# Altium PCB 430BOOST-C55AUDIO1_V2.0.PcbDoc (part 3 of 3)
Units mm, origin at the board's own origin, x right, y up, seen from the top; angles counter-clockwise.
Board outline 50.8 x 84 mm, 4 copper layers (Top Layer, GND, POW, Bottom Layer); 272 components, 169 nets, 833 pads, 607 vias.
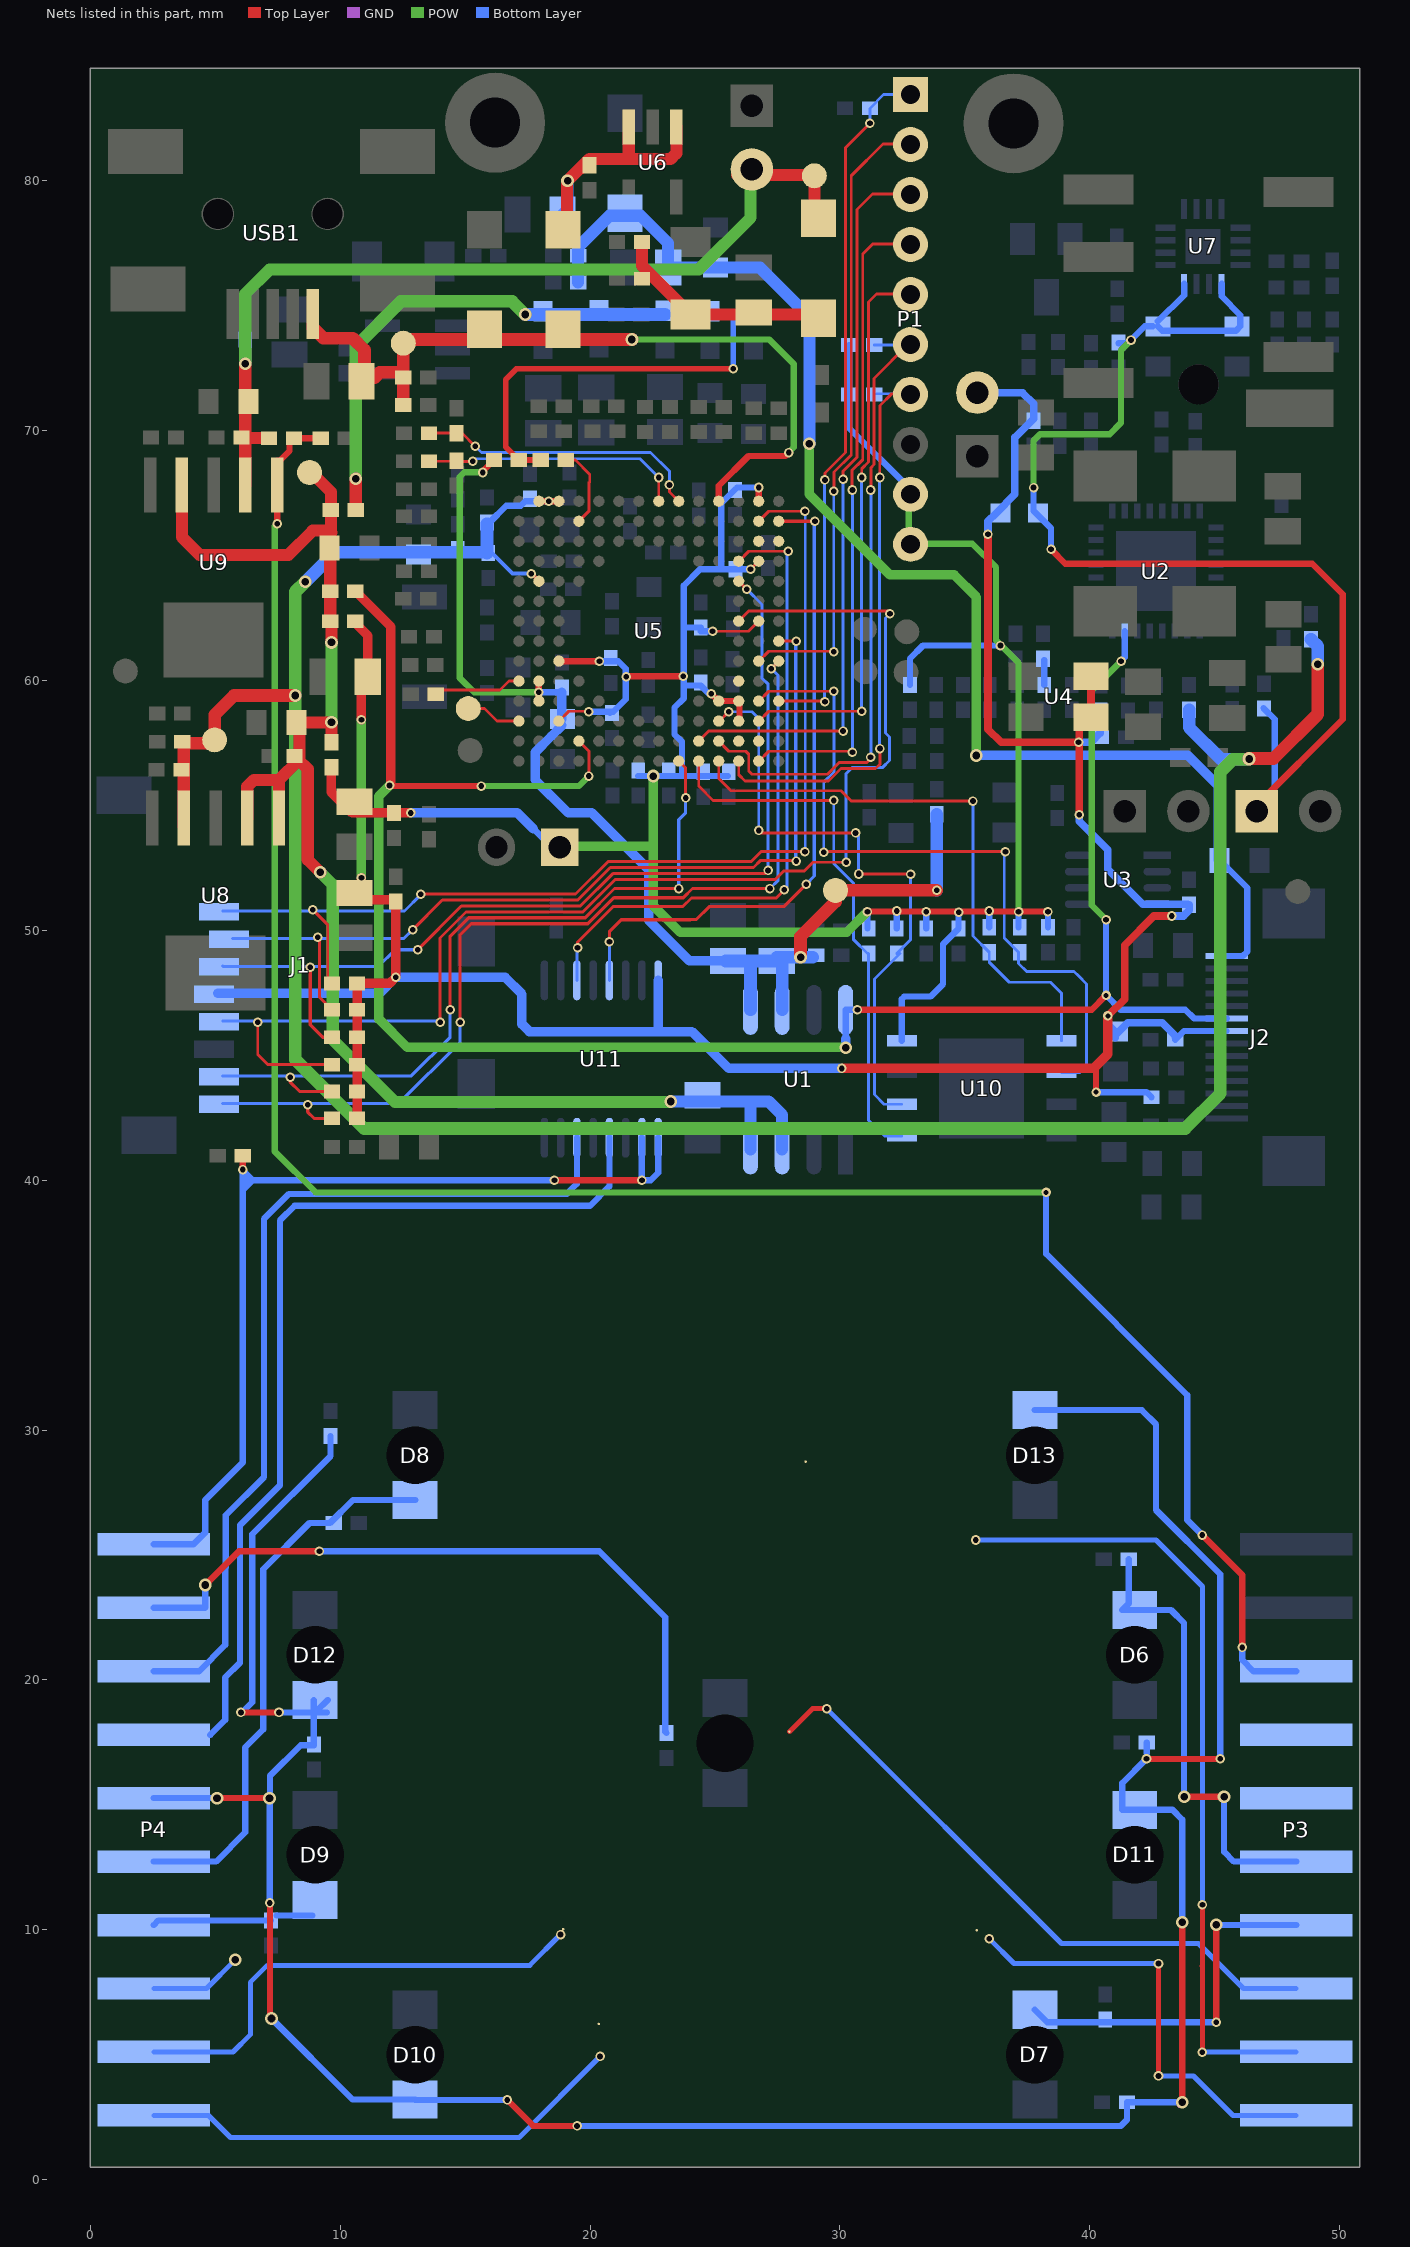
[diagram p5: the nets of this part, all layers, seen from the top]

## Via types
v1: diameter 0.381, hole 0.229, Top Layer to Bottom Layer, 549 vias
v2: diameter 0.508, hole 0.305, Top Layer to Bottom Layer, 42 vias
v3: diameter 0.381, hole 0.203, Top Layer to Bottom Layer, 16 vias

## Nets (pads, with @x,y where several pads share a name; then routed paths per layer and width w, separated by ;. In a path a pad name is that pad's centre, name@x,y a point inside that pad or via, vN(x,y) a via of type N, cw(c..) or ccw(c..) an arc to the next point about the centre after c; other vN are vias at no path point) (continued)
P1.0: P4.2 R87.2 | length 28
  Top Layer w0.25: v2(4.6,23.8) 5.95,25.15 8.6,25.15 v1(9.17,25.15)
  Bottom Layer w0.25: P4.2@2.54,22.89 4.59,22.89 4.6,22.9 v2(4.6,23.8) ; v1(9.17,25.15) 15.06,25.15 ; 15.43,25.15 15.06,25.15 ; R87.2@23.06,17.88 23.01,17.93 23.01,22.51 20.37,25.15 15.06,25.15
P1.1_RX: P4.3 U11.6 | length 36.3
  Bottom Layer w0.25: P4.3@2.54,20.35 4.35,20.35 5.4,21.4 5.4,24.48 5.42,24.5 5.42,26.59 6.95,28.12 6.95,33.9 ; 6.95,34.252 6.95,33.9 ; U11.6@19.475,41.7 19.475,39.85 19.075,39.45 7.95,39.45 6.95,38.45 6.95,33.9
P1.2_TX: P4.4 U11.4 | length 37.4
  Bottom Layer w0.25: 4.8,17.8 5.4,18.4 5.4,20.1 5.99,20.69 5.99,26.19 7.59,27.79 7.59,38.39 8.175,38.975 20,38.975 20.775,39.75 U11.4@20.775,41.7
P1.3: D10.2 D11.2 D12.2 D13.2 P4.5 R83.1 R84.1 R85.1 R86.1 | length 113.5
  Top Layer w0.25: v2(5.07,15.27) v2(7.17,15.27) ; v1@6.05,18.7 v1(7.55,18.7) ; v1@7.19,11.075 7.19,6.51 v2(7.25,6.45) ; v1(16.69,3.19) 17.73,2.15 v1(19.48,2.15) ; v1(42.27,16.84) v1(45.22,16.84) ; v2(43.7,3.1) v2(43.7,10.3)
  GND w0.25: v2(7.17,15.27) v2@7.2,15.3 ; v2@43.6,3 v2(43.7,3.1)
  Bottom Layer w0.25: P4.5@2.54,15.27 v2(5.07,15.27) ; v1(6.025,18.7) 6.075,18.7 6.48,19.105 6.48,25.83 9.61,28.96 R84.1@9.61,29.76 ; v1(7.175,11.075) v2@7.175,15.255 ; v2@7.19,15.27 7.19,16.16 8.42,17.39 R85.1@8.95,17.39 ; v2(7.25,6.45) 10.49,3.21 12.99,3.21 D10.2@13,3.2 13.01,3.19 v1(16.69,3.19) ; v1(7.55,18.7) D12.2@9.47,18.7 ; R85.1@8.94,17.39 D12.2@8.94,19.19 ; D12.2@9.04,18.74 9.49,19.19 D12.2@9.5,19.2 ; v1(19.48,2.15) 41.25,2.15 41.49,2.39 R86.1@41.49,3.1 v2(43.7,3.1) ; D13.2@37.8,30.8 42.075,30.8 42.65,30.225 42.65,26.8 45.22,24.23 v1(45.22,16.84) ; v1@42.28,16.84 42.28,16.85 v1(42.27,16.84) 41.3,15.87 41.3,14.8 D11.2@41.8,14.8 43.31,14.8 43.7,14.41 43.7,10.58 v2(43.7,10.3) ; 42.28,17.07 R83.1@42.28,17.5
P1.4: D8.2 P4.6 R15.2 | length 22.2
  Bottom Layer w0.25: P4.6@2.54,12.73 5.03,12.73 6.2,13.9 6.2,17.3 6.92,18.02 6.92,24.43 8.77,26.28 9.59,26.28 10.51,27.2 D8.2@13,27.2
P1.5: D9.2 P4.7 R17.2 | length 6.2
  Bottom Layer w0.25: P4.7@2.54,10.19 2.725,10.375 6.1,10.375 R17.2@7.225,10.375 ; R17.2@7.45,10.575 D9.2@8.89,10.575
P1.6: D7.2 P3.7 R18.2 | length 14.6
  Top Layer w0.25: v1(45.06,6.3) 45.06,9.3 v2(45.06,10.2)
  Bottom Layer w0.25: D7.2@37.8,6.8 38.3,6.3 v1(45.06,6.3) ; v2(45.06,10.2) 45.07,10.19 P3.7@48.26,10.19
P1.7: D6.2 P3.6 R78.2 | length 18.6
  Top Layer w0.25: v2(43.775,15.325) v2(45.375,15.325)
  Bottom Layer w0.25: R78.2@41.56,24.83 41.56,23.06 41.3,22.8 D6.2@41.8,22.8 43.25,22.8 43.775,22.275 43.775,18.5 43.775,16.375 v2(43.775,15.325) ; v2(45.375,15.325) 45.375,13.125 45.77,12.73 P3.6@48.26,12.73
P2.0: P4.8 | length 3.7
  Bottom Layer w0.2: P4.8@2.54,7.65 4.65,7.65 v2(5.8,8.8)
P2.1: J4.1 P4.9 | length 19.5
  Top Layer w0.2: v1(18.82,9.81) v1@18.82,9.9
  Bottom Layer w0.2: P4.9@2.54,5.11 5.71,5.11 6.4,5.8 6.4,7.9 7.08,8.58 7.9,8.58 17.59,8.58 v1(18.82,9.81)
P2.2: J5.1 P4.10 | length 19.6
  Bottom Layer w0.2: P4.10@2.54,2.57 4.73,2.57 5.61,1.69 17.16,1.69 v1(20.4,4.93)
P2.3: J6.1 P3.10 | length 17.8
  Top Layer w0.2: v1(42.75,4.15) v1(42.75,8.65)
  Bottom Layer w0.2: v1(35.98,9.64) 36.97,8.65 40.9,8.65 41.65,8.65 v1(42.75,8.65) ; v1(42.75,4.15) 44.15,4.15 45.73,2.57 P3.10@48.26,2.57
P2.4: J7.1 P3.9 | length 34.6
  Top Layer w0.2: 44.5,8.55 44.51,8.56 ; v1@44.51,5.19 44.51,8.56 ; 44.51,8.56 44.51,8.575 ; 44.51,8.575 44.51,9.2 v1(44.51,11) 44.51,8.575
  Bottom Layer w0.2: v1(35.44,25.6) 42.65,25.6 44.51,23.74 v1(44.51,11) ; v1@44.51,5.19 44.59,5.11 P3.9@48.26,5.11
  other v1: 44.5,5.1
P2.5: J8.1 P3.8 | length 25.3
  Top Layer w0.2: J8.1@27.98,17.93 28.9,18.85 v1(29.47,18.85)
  Bottom Layer w0.2: v1(29.47,18.85) 38.87,9.45 44.35,9.45 46.15,7.65 P3.8@48.26,7.65
P2.7_PWR_EN: P3.3 R55.1 R56.2 U9.1 | length 111
  Top Layer w0.25: v1(7.475,66.275) U9.1@7.475,67.825 ; U9.1@7.475,67.15 U9.1@7.475,67.825 ; R56.2@9.225,69.7 R55.1@8.15,69.7 7.975,69.525 7.975,69.2 7.575,68.8 7.475,68.8 U9.1@7.475,67.825 ; v1(44.5,25.8) 46.1,24.2 v1(46.1,21.3)
  POW w0.25: 7.375,41.4 7.375,65.825 ; v1(7.475,66.275) 7.375,66.175 7.375,65.825 ; v3(38.25,39.51) 9.015,39.51 7.375,41.15 7.375,65.825
  Bottom Layer w0.25: v3(38.25,39.51) 38.25,37.05 43.9,31.4 43.9,26.4 v1(44.5,25.8) ; v1(46.1,21.3) 46.1,20.8 46.55,20.35 P3.3@48.26,20.35
RST: P3.5
RTC_CLKOUT: TP9.1 U5.A3 | length 2.2
  Top Layer w0.114: TP9.1@15.125,58.875 15.775,58.875 16.275,58.375 U5.A3@17.15,58.375
SD_CLK: J1.5 R69.1 U5.M8 | length 52.1
  Top Layer w0.114: v1(6.7,46.325) 6.7,45.025 7.1,44.625 7.7,44.625 ; 7.4,44.625 7.7,44.625 ; R69.1@9.675,44.625 7.7,44.625 ; v1(14,46.325) 14,49.699 15.04,50.739 19.71,50.739 21.009,52.038 27.413,52.038 27.75,52.375 28.575,52.375 28.925,52.725 v1(30.25,52.725) ; U5.M8@25.95,62.375 26.354,62.779 31.896,62.779 v1(32,62.675)
  Bottom Layer w0.114: J1.5@5.3,46.375 13.95,46.375 v1(14,46.325) ; v1(30.25,52.725) 30.25,56.275 30.5,56.525 31.713,56.525 31.988,56.8 31.988,57.737 31.825,57.9 31.825,62.5 v1(32,62.675)
SD_CMD: J1.3 R70.1 U5.M10 | length 38.9
  Top Layer w0.127: v1(8.8,48.525) 8.8,46.225 9.3,45.725 R70.1@9.675,45.725 ; v1(13.1,49.225) 14.849,50.974 19.612,50.974 20.912,52.273 26.998,52.273 v1(27.125,52.4) ; U5.M10@25.95,63.975 v1(26.275,63.65)
  Bottom Layer w0.127: J1.3@5.3,48.575 5.318,48.557 11.532,48.557 12.2,49.225 v1(13.1,49.225) ; v1(26.275,63.65) 26.882,63.043 26.882,60.093 27.125,59.85 v1(27.125,52.4)
SD_DATA0: J1.7 R68.1 U5.J1 | length 31.1
  Top Layer w0.127: v1(8,44.125) 8,43.925 8.375,43.55 R68.1@9.675,43.55 ; v1(14.4,46.825) 14.4,49.766 15.138,50.504 19.807,50.504 20.978,51.675 v1(23.55,51.675) ; U5.J1@23.55,56.775 23.825,56.5 v1(23.825,55.3)
  Bottom Layer w0.127: J1.7@5.3,44.175 12.85,44.175 14.4,45.725 v1(14.4,46.825) ; v1(23.55,51.675) 23.55,54.425 23.825,54.7 v1(23.825,55.3)
SD_DATA1: J1.8 R67.1 U5.P6 | length 38.8
  Top Layer w0.127: v1(8.7,43.025) 8.7,42.725 8.95,42.475 R67.1@9.675,42.475 ; v1(14.8,46.325) 14.8,49.825 15.238,50.263 19.907,50.263 20.951,51.307 23.732,51.307 24.1,51.675 v1(27.2,51.675) ; v1(27.25,60.475) U5.P6@27.55,60.775
  Bottom Layer w0.127: J1.8@5.3,43.075 12.35,43.075 14.8,45.525 v1(14.8,46.325) ; v1(27.2,51.675) 27.525,52 27.525,60.2 v1(27.25,60.475)
SD_DATA2: J1.1 R72.1 U5.N13 | length 43.3
  Top Layer w0.114: v1(8.9,50.825) 9.5,50.225 9.5,48.05 R72.1@9.675,47.875 ; v1(13.225,51.45) 19.415,51.45 20.714,52.749 26.442,52.749 26.856,53.163 v1@28.6,53.163 ; U5.N13@26.75,66.375 27.15,66.775 v1(28.6,66.775) v1@28.65,66.775
  GND w0.114: v1@13.2,51.425 v1(13.225,51.45)
  Bottom Layer w0.114: J1.1@5.3,50.775 12.575,50.775 v1@13.225,51.425 ; v1(28.6,53.15) 28.612,53.162 28.612,66.737 v1@28.65,66.775
SD_DATA3: J1.2 R71.1 U5.P7 | length 36.5
  Top Layer w0.127: v1(9.1,49.725) 9.168,49.657 9.168,47.332 R71.1@9.675,46.825 ; v1(12.9,50.025) 14.09,51.215 19.512,51.215 20.812,52.514 26.539,52.514 26.825,52.8 v1@28.225,52.8 ; U5.P7@27.55,61.575 v1(28.25,61.575)
  Bottom Layer w0.127: J1.2@5.7,49.675 12.55,49.675 v1(12.9,50.025) ; v1@28.232,61.557 28.232,52.793 v1(28.25,52.775) ; v1@28.25,61.557 v1(28.25,61.575)
SPI_CLK: R65.2 U5.L3 U10.6 | length 24.9
  Top Layer w0.114: U5.L3@25.175,58.375 v1(25.55,58.75) ; v1@26.626,54 v1(26.75,54) 26.85,53.9 v1(30.625,53.9) ; v1(30.75,52.25) v1(32.825,52.25)
  POW w0.114: v1(30.75,52.25) v1(30.75,52.275)
  Bottom Layer w0.114: v1(25.55,58.75) 26.475,58.75 26.75,58.475 v1(26.75,54) ; v1(30.625,53.9) 30.75,53.775 v1(30.75,52.275) ; R65.2@32.275,49.075 32.825,49.625 v1(32.825,52.25) ; R65.2@32.4,49.075 31.379,48.054 31.379,43.425 31.764,43.04 U10.6@32.475,43.04
SPI_CS0: R62.2 U5.L1 U10.1 | length 23.3
  Top Layer w0.114: U5.L1@25.15,56.775 25.15,56.075 25.638,55.587 26.801,55.587 30.038,55.587 30.45,55.175 v1(35.325,55.175)
  Bottom Layer w0.114: v1(35.325,55.175) 35.325,49.775 R62.2@35.975,49.125 35.975,48.725 36.775,47.925 38.425,47.925 38.875,47.475 U10.1@38.875,45.58
SPI_CS1: U5.M2
SPI_CS2: U5.N2
SPI_CS3: U5.M5
SPI_RX: R63.2 U5.N4 U10.2 | length 29.2
  Top Layer w0.114: U5.N4@26.75,59.175 26.757,59.175 27.154,59.571 v1(29.75,59.571) ; v1(29.35,53.125) 29.375,53.15 v1(36.625,53.15)
  Bottom Layer w0.114: v1(29.35,53.125) 29.35,55.925 29.762,56.337 v1@29.762,59.559 ; v1(36.625,53.15) 36.575,53.1 36.575,49.7 37.15,49.125 37.15,48.675 37.475,48.35 39.375,48.35 39.562,48.163 39.875,47.85 39.875,44.575 39.61,44.31 U10.2@38.875,44.31
SPI_TX: R66.2 U5.K1 U10.5 | length 21.7
  Top Layer w0.114: U5.K1@24.35,56.775 24.35,55.775 24.925,55.2 v1(29.75,55.2)
  Bottom Layer w0.114: v1(29.75,55.2) 29.75,52.675 30.55,51.875 30.55,49.625 R66.2@31.1,49.075 ; R66.2@31.15,49.075 31.15,42.4 31.78,41.77 U10.5@32.475,41.77 U10.5@32.38,41.77
TARGET_EMU0: P1.6 R34.1 U5.L2 | length 25.9
  Top Layer w0.114: U5.L2@25.15,57.575 25.554,57.171 26.229,57.171 26.354,57.046 26.354,56.375 26.479,56.25 29.5,56.25 29.975,56.725 31.071,56.725 31.25,56.904 v1@31.24,56.915 ; v1@31.237,67.637 31.237,68.517 31.368,68.648 31.368,72.093 P1.6@32.75,73.475 ; v1@31.24,56.915 v1(31.227,56.928) 31.214,56.915 v1@31.24,56.915
  POW w0.114: v1(31.227,56.928) v1@31.249,56.95
  Bottom Layer w0.114: v1@31.237,56.928 v1@31.237,67.613 ; R34.1@31.375,73.425 P1.6@32.7,73.425
  other v1: 31.225,67.625
TARGET_EMU1: P1.7 R33.1 U5.M1 | length 24.3
  Top Layer w0.114: U5.M1@25.95,56.775 25.95,56.225 26.2,55.975 29.548,55.975 30.048,56.475 31.425,56.475 31.6,56.65 v1(31.6,57.275) ; 31.597,69.378 31.597,68.158 v1@31.602,68.153 ; 31.6,68.703 31.6,71 32.075,71.475 P1.7@32.75,71.475
  POW w0.114: v1@31.602,68.152 v1@31.602,68.153
  Bottom Layer w0.114: R33.1@31.375,71.45 31.4,71.475 P1.7@32.75,71.475 ; v1(31.6,57.275) 31.588,57.287 31.588,68.113 v1(31.6,68.125)
TARGET_PWR_GOOD: J2.9 R53.1 U1.8 U2.31 U5.D2 | length 79.4
  Top Layer w0.114: U5.D2@19.55,57.575 19.95,57.175 v1(19.95,56.175)
  Top Layer w0.254: v1@12.025,55.775 v1(15.65,55.775) ; v1(30.7,46.825) 40.075,46.825 v3(40.652,47.4) v3(40.652,47.4)
  Top Layer w0.381: R53.1@10.6,63.575 12.025,62.15 12.025,62.128 v1@12.025,55.85
  POW w0.254: v1(15.65,55.775) 19.55,55.775 v1(19.95,56.175) ; v1(40.652,50.423) 40.075,51 40.075,59.6 v1(41.25,60.775)
  POW w0.381: v1(11.975,55.8) 11.55,55.375 11.55,46.45 12.68,45.32 v2@30.215,45.32
  Bottom Layer w0.254: 30.236,45.661 U1.8@30.236,46.819 ; U1.8@30.236,46.825 v1(30.7,46.825) ; v1(40.652,50.423) v3(40.652,47.4) 41.227,46.825 43.825,46.825 44.175,46.475 J2.9@45.475,46.475 ; v1(41.25,60.775) 41.4,60.925 U2.31@41.4,61.975
  Bottom Layer w0.381: v2(30.23,45.305) 30.23,45.655
TARGET_TCK: P1.5 U5.N3 | length 22.3
  Top Layer w0.114: U5.N3@26.75,58.375 26.757,58.375 27.154,58.771 29.626,58.771 ; 29.779,58.771 29.626,58.771 ; v1@30.852,68.078 30.852,68.127 v1@30.875,68.15 ; v1@30.871,58.771 29.626,58.771 ; v1(30.875,68.125) v1@30.875,68.15 ; P1.5@32.3,75.475 31.464,75.475 31.139,75.15 31.139,68.743 30.875,68.478 v1@30.875,68.15
  Bottom Layer w0.114: v1(30.875,58.775) 30.863,58.787 30.863,68.113 v1(30.875,68.125)
TARGET_TDI: P1.3 U5.K2 | length 29
  Top Layer w0.114: U5.K2@24.35,57.575 24.75,57.975 v1(30.125,57.975) ; v1(30.125,68.05) 30.125,68.375 30.682,68.932 30.682,78.85 31.307,79.475 P1.3@32.3,79.475
  POW w0.114: v1(30.125,57.975) v1@30.15,57.95
  Bottom Layer w0.114: v1(30.125,57.975) v1(30.125,68.05)
TARGET_TDO: P1.4 U5.N1 | length 25.6
  Top Layer w0.114: U5.N1@26.75,56.775 26.757,56.775 27.154,57.171 30.454,57.171 v1(30.5,57.125) ; v1@30.49,67.635 30.49,68.416 30.911,68.838 30.911,77.075 31.311,77.475 P1.4@32.3,77.475
  Bottom Layer w0.114: v1(30.5,57.125) v1(30.5,67.625)
TARGET_TMS: P1.2 U5.N6 | length 25.9
  Top Layer w0.114: U5.N6@26.75,60.775 26.757,60.775 27.154,61.171 29.051,61.171 ; v1@29.604,61.171 29.051,61.171 ; v1@29.729,61.171 29.051,61.171 ; v1(29.75,67.575) 29.762,67.587 29.762,68.339 30.454,69.03 30.454,80.204 31.725,81.475 P1.2@32.75,81.475
  POW w0.114: v1@29.723,67.625 29.75,67.598 v1(29.75,67.575)
  Bottom Layer w0.114: v1(29.75,61.15) v1(29.75,67.575)
TARGET_TRSTN: P1.1 R6.2 U5.P4 | length 28.2
  Top Layer w0.114: U5.P4@27.55,59.175 29.4,59.175 v1(29.4,59.15) ; v1(29.4,68.028) 29.4,68.3 30.225,69.125 30.225,81.325 v1(31.2,82.3)
  Bottom Layer w0.114: v1(29.4,59.15) 29.388,59.162 29.388,68.016 v1(29.4,68.028) ; v1(31.2,82.3) R6.2@31.2,82.9 31.75,83.45 P1.1@32.825,83.45
TEST: P3.4
UART_CTS: U5.P12
UART_RTS: U5.N12
UART_RX: U5.P13 U11.13 | length 27.4
  Top Layer w0.127: v1(20.775,49.55) 20.775,49.95 21.25,50.425 24.025,50.425 ; 24.025,50.44 24.261,50.44 24.771,50.95 26.551,50.95 27.75,50.95 v1(28.65,51.85) ; U5.P13@27.55,66.375 v1(29,66.375)
  Bottom Layer w0.127: U11.13@20.775,48 v1(20.775,49.55) ; v1(28.65,51.85) 28.975,52.175 28.975,52.902 ; 28.975,52.225 28.975,52.902 ; v1(29,66.375) 28.975,66.35 28.975,52.902
UART_TX: U5.M11 U11.11 | length 26.5
  Top Layer w0.114: v1(19.5,49.3) 19.5,49.523 20.927,50.95 23.707,50.95 24.057,51.3 27.45,51.3 v1(27.775,51.625) ; U5.M11@25.95,64.775 25.957,64.775 26.354,65.171 v1@27.92,65.171
  POW w0.114: v1@19.475,49.275 v1(19.5,49.3)
  Bottom Layer w0.114: U11.11@19.475,48 v1@19.475,49.3 ; v1(27.775,51.625) 27.888,51.738 27.888,65.14 v1(27.926,65.178)
USB_CLK_12MHZ: R21.2 R26.1 | length 1
  Bottom Layer w0.25: R21.2@38.175,59.825 R26.1@38.175,60.825
USB_DM: C107.2 R11.1 U5.J14 | length 11.6
  Top Layer w0.114: R11.1@13.6,69.9 C107.2@14.65,69.9 14.875,69.9 v1(15.4,69.375) ; v1@23.15,67.802 v1(23.176,67.828) 23.176,67.549 U5.J14@23.55,67.175
  Bottom Layer w0.114: v1(15.4,69.375) 15.65,69.125 22.425,69.125 23.176,68.374 v1(23.176,67.828)
USB_DP: C11.2 R48.1 U5.H14 | length 10.6
  Top Layer w0.114: R48.1@13.55,68.775 C11.2@14.65,68.775 ; C11.2@14.65,68.8 14.679,68.771 v1(15.304,68.771) ; U5.H14@22.75,67.175 v1(22.75,68.125)
  Bottom Layer w0.114: v1(15.304,68.771) 15.35,68.771 15.454,68.875 22,68.875 22.7,68.175 v1(22.75,68.125) v1@22.75,68.175
USB_LDO_OUT: L5.1 L6.1 R43.1 R44.2 | length 17.5
  Top Layer w0.229: R43.1@18.025,68.825 R44.2@17.15,68.825 16.625,69.35 16.625,72.05 17.05,72.475 v1(25.725,72.475)
  Bottom Layer w0.229: v1(25.725,72.475) 25.725,73.628 25.725,74.649
  Bottom Layer w0.254: L5.1@24.8,74.649 L6.1@26.55,74.649
USB_LDO_OUT_REG: R43.2 U5.D13 | length 3.3
  Top Layer w0.114: R43.2@19.025,68.825 19.412,68.825 19.987,68.25 19.987,67.95 19.95,67.913 19.95,66.775 U5.D13@19.55,66.375
USB_VBUS: C21.1 C22.1 D1.1 D2.2 R25.2 TP2.1 U5.L14 USB1.1 | length 32.2
  Top Layer w0.254: U5.L14@25.15,67.175 25.15,67.795 26.341,68.987 27.812,68.987 v1(27.95,69.125)
  Top Layer w0.508: USB1.1@8.9,74.675 8.9,74.125 9.325,73.7 10.5,73.7 10.975,73.225 C21.1@10.975,72.125 ; C21.1@10.975,71.925 C21.1@10.975,72.125 ; C22.1@12.525,71.025 TP2.1@12.525,73.5 12.675,73.65 19.025,73.65 v2(21.675,73.65) ; R25.2@12.525,72.125 12.313,72.337 11.594,72.337 11.382,72.125 C21.1@10.975,72.125
  POW w0.254: v2(21.675,73.65) 27.175,73.65 28.157,72.668 28.157,69.332 v1(27.95,69.125)
V3.3A: C109.2 C110.2 JP2.1 L1.2 R4.2 R91.2 U7.13 U7.16 | length 47.6
  Top Layer w0.254: v1(38.45,65.25) 39.025,64.675 48.9,64.675 50.125,63.45 50.125,58.445 JP2.1@46.655,54.975
  POW w0.254: v1(37.749,67.724) 37.749,69.599 38.007,69.857 40.792,69.857 41.25,70.314 41.25,73.225 v1(41.65,73.625)
  Bottom Layer w0.254: v1(37.749,67.724) 37.749,66.801 38.45,66.1 v1(38.45,65.25) ; R91.2@41.15,73.5 41.525,73.5 42.2,74.175 C110.2@42.525,74.175 ; C110.2@42.725,74.175 42.9,74 45.85,74 46.025,74.175 46.025,74.625 45.275,75.375 U7.13@45.275,75.875 ; C110.2@42.725,74.375 43.775,75.425 U7.16@43.775,75.875 ; JP2.1@46.73,55.05 47.4,55.72 47.4,58.45 R4.2@46.975,58.875 R4.2@46.95,58.9
V13: C101.1 C103.2 C104.2 C105.1 D5.2 J2.14 R80.2 | length 53.5
  Top Layer w0.381: v2(28.775,69.475) v2@28.8,69.5
  POW w0.381: v2(28.775,69.475) 28.775,67.45 32,64.225 34.575,64.225 35.461,63.339 v2(35.461,57)
  Bottom Layer w0.25: C101.1@45.2,52.8 46.3,51.7 46.3,49.577 46.3,49.15 46.125,48.975 J2.14@45.475,48.975
  Bottom Layer w0.381: v2(35.461,57) 43.925,57 45.15,55.775 C101.1@45.15,52.8
  Bottom Layer w0.483: R80.2@19.525,75.925 C103.2@19.525,77 19.525,77.35 20.775,78.6 22.025,78.6 23.125,77.5 C105.1@23.125,76.525 C104.2@25.025,76.525 26.8,76.525 28.775,74.55 v2(28.775,69.475)
VCC_1V3: C26.2 C27.2 C77.1 C78.1 R7.1 R44.1 R51.2 TP6.1 U1.5 U1.6 U5.B4 U5.B5 | length 48.9
  Top Layer w0.25: U5.B4@17.95,59.175 v1(17.95,59.525) U5.B5@17.95,59.975
  Top Layer w0.254: v1(15.7,68.325) 15.7,68.375 R44.1@16.15,68.825
  Top Layer w0.508: v2(28.425,48.925) 28.425,49.75 29.825,51.15 TP6.1@29.825,51.6 v1(33.875,51.6)
  POW w0.254: v1(15.7,68.325) 15.693,68.332 14.968,68.332 14.787,68.15 14.787,60.103 15.364,59.525 v1(17.95,59.525)
  Bottom Layer w0.25: C78.1@26.8,48.875 C78.1@27.201,48.875 ; C78.1@27.69,48.775 C78.1@27.69,48.79 ; C78.1@27.69,48.875 C78.1@27.925,48.875
  Bottom Layer w0.254: v1(17.95,59.525) C27.2@18.675,59.525
  Bottom Layer w0.381: C26.2@18.875,58.2 18.445,57.77 17.8,57.125 17.8,56.025 19.125,54.7 20.075,54.7 22.341,52.434 22.341,50.409 23.975,48.775 C77.1@25.525,48.775 ; C26.2@18.875,58.45 C27.2@18.875,59.525
  Bottom Layer w0.508: C77.1@25.425,48.775 C77.1@25.525,48.775 C78.1@27.475,48.775 ; U1.5@26.42,46.819 26.42,48.495 26.42,48.695 ; C78.1@27.375,48.775 C78.1@27.475,48.775 ; C78.1@27.475,48.925 v2(28.425,48.925) R51.2@28.9,48.925 ; C78.1@27.615,48.715 27.555,48.775 C78.1@27.475,48.775 ; U1.6@27.69,46.819 27.69,48.775 C78.1@27.69,48.875 ; v1(33.875,51.6) R7.1@33.875,54.65
VCC_1V8: C59.2 C60.2 C61.2 C79.2 C82.2 R1.1 R2.2 R20.2 R41.2 TP13.1 U5.B10 U5.B14 U5.C14 U8.4 | length 107
  Top Layer w0.152: v1(17.651,64.278) U5.B10@17.95,63.979
  Top Layer w0.254: U5.B14@17.95,67.175 v1(18.35,67.175) U5.C14@18.75,67.175
  Top Layer w0.508: U8.4@3.74,54.2 U8.4@3.74,54.5 3.74,55.978 3.74,57.485 TP13.1@4.885,57.485 ; TP13.1@4.975,57.625 4.975,58.625 5.75,59.4 v2(8.2,59.4) ; v2(46.375,56.85) v2(46.375,56.875) 47.35,56.875 49.125,58.65 v2@49.125,60.625
  POW w0.508: v2(8.6,63.95) 8.2,63.55 v2(8.2,59.4) 8.2,44.825 10.959,42.066 43.816,42.066 45.225,43.475 45.225,56.35 45.725,56.85 v2(46.375,56.85)
  Bottom Layer w0.152: C61.2@15.85,65.025 C61.2@15.85,65.1 ; C61.2@15.875,65.1 C61.2@15.925,65.1 16.075,65.1 16.897,64.278 17.451,64.278 v1(17.651,64.278) v1@17.604,64.325
  Bottom Layer w0.254: C60.2@15.825,66.325 15.975,66.325 16.65,67 17.225,67 17.4,67.175 v1(18.35,67.175) 18.375,67.175 v1@18.362,67.162
  Bottom Layer w0.508: v2(8.6,63.95) 9.784,65.134 13.041,65.134 13.125,65.134 15.251,65.134 ; 15.491,65.134 15.251,65.134 ; C61.2@15.816,65.134 15.251,65.134 ; C61.2@15.875,65.1 C60.2@15.875,66.275 ; R1.1@43.975,58.825 43.975,58.6 43.975,58.125 45.25,56.85 v2(46.375,56.85) ; R2.2@48.85,61.65 48.9,61.6 49.125,61.375 v2(49.125,60.65)
  other v2: 46.375,56.875
VCC_3V3: C14.2 C85.1 C108.2 C201.2 C206.1 C210.2 C211.2 J1.4 J2.8 JP1.2 L1.1 R3.1 R22.1 R59.2 R67.2 R68.2 R69.2 R70.2 R71.2 R72.2 R76.2 U3.4 U4.1 U4.4 U11.16 | length 115.7
  Top Layer w0.25: 40.15,44.475 40.25,44.375 v3(40.25,43.525)
  Top Layer w0.305: v1(35.925,65.85) 35.925,58.05 36.45,57.525 v1(39.55,57.525) ; v1(39.575,54.625) 39.575,58.05 U4.4@40.05,58.525 U4.1@40.05,60.175 ; v3(40.725,46.575) 41.402,47.252 41.402,49.412 42.565,50.575 v1(43.275,50.575)
  Top Layer w0.381: R59.2@10.6,62.3 11.1,61.8 C85.1@11.1,60.15 10.85,59.9 v1(10.85,58.425) ; R67.2@10.675,42.475 R68.2@10.675,43.55 R69.2@10.675,44.625 R70.2@10.675,45.725 R71.2@10.675,46.825 R72.2@10.675,47.875 11.975,47.875 v1(12.225,48.125) 12.225,51.075 C201.2@12.25,51.05 ; C206.1@10.7,51.225 C201.2@12.25,51.225 ; C206.1@10.85,51.25 v1(10.85,52.1) ; v1(30.075,44.475) 40.15,44.475 40.725,45.05 v3(40.725,46.575)
  POW w0.305: v1@39.575,54.6 v1(39.575,54.625)
  POW w0.381: v1(10.85,52.1) v1(10.85,58.425)
  Bottom Layer w0.25: v3(40.25,43.525) 42.275,43.525 R76.2@42.475,43.325 ; C210.2@43.425,45.625 43.775,45.975 J2.8@45.475,45.975
  Bottom Layer w0.305: JP1.2@35.25,71.52 37.305,71.52 37.75,71.075 37.75,70.475 37,69.725 37,67.449 36.251,66.7 35.925,66.374 v1(35.925,65.85) ; v1(39.55,57.525) 40.05,57.525 40.425,57.9 R22.1@40.425,58.8 ; v1(39.575,54.625) 39.575,54.375 40.725,53.225 40.725,52.45 42.125,51.05 U3.4@42.7,51.05 43.925,51.05 C108.2@43.975,51 ; v3(40.725,46.575) 40.725,46.25 C211.2@41.025,45.95 ; C211.2@41.025,45.7 41.025,45.8 41.525,46.3 42.9,46.3 43.425,45.775 C210.2@43.425,45.725 ; v1(43.275,50.575) 43.75,50.575 43.975,50.8 C108.2@43.975,51 ; C108.2@43.975,51.025 C108.2@43.975,51
  Bottom Layer w0.381: J1.4@5.1,47.475 11.575,47.475 v1(12.225,48.125) 14.726,48.125 ; 14.15,48.125 14.726,48.125 ; U11.16@22.725,48 22.725,45.95 ; v1(30.075,44.475) 25.55,44.475 24.075,45.95 22.725,45.95 ; 14.726,48.125 16.6,48.125 17.275,47.45 17.275,46.25 17.575,45.95 22.725,45.95
VCC_3V3_PWR: C76.1 C80.2 C81.2 C89.2 R53.2 R57.1 R58.1 R59.1 TP8.1 U1.3 U1.4 U8.1 U8.2 U9.4 | length 63.3
  Top Layer w0.483: U9.4@3.665,67.825 3.665,65.735 4.375,65.025 7.925,65.025 8.9,66 9.575,66 9.6,65.975 ; U8.2@6.28,54.5 6.28,55.755 6.55,56.025 7.55,56.025 ; U8.1@7.55,54.5 7.55,56.025 ; C80.2@8.175,56.975 C80.2@8.337,56.813 ; C81.2@8.25,58.325 C81.2@8.375,58.325 ; 8.675,56.475 C80.2@8.337,56.813 ; TP8.1@8.775,68.4 9.625,67.55 9.625,67.45 9.625,66 ; v2(9.2,52.325) 8.7,52.825 8.7,56.45 C80.2@8.337,56.813 ; R59.1@9.6,62.3 R59.1@9.6,62.375 9.6,64.025 9.6,65.975 ; R58.1@9.65,57.525 v2(9.65,58.325) C81.2@8.375,58.325 ; v2(9.65,61.525) R59.1@9.65,62.375 ; 9.65,65.925 9.6,65.975 ; 7.55,56.025 C80.2@8.337,56.813 ; C80.2@8.337,56.813 8.375,56.85 C81.2@8.375,58.325
  POW w0.483: v2(9.2,52.325) 9.7,51.825 9.7,45.625 12.2,43.125 14.6,43.125 v2@23.2,43.125 ; v2(9.65,58.325) v2(9.65,61.525) ; v2@23.2,43.15 v2(23.225,43.15)
  Bottom Layer w0.483: v2(23.225,43.15) 26.42,43.15 ; U1.4@26.42,41.231 26.42,43.15 ; U1.3@27.69,41.231 27.69,42.61 27.15,43.15 26.42,43.15
  other v2: 9.65,61.525
VCC_3V3_USB: L3.1 L4.1 L7.1 R57.2 | length 19.7
  Top Layer w0.508: R57.2@10.625,66.825 v2(10.625,68.075)
  POW w0.508: v2(10.625,68.075) 10.625,73.375 12.425,75.175 16.875,75.175 v2(17.4,74.65)
  Bottom Layer w0.508: v2@17.551,74.649 L4.1@23,74.649
VCC_3V6: C87.2 C88.2 D4.2 JP3.2 R55.2 R79.1 TP5.1 U9.2 | length 38.1
  Top Layer w0.483: C88.2@6.05,69.7 C88.2@6.2,69.7 ; U9.2@6.2,67.83 C88.2@6.2,69.7 ; v2(6.2,72.675) 6.2,70.35 C88.2@6.2,69.7 ; R55.2@7.15,69.7 C88.2@6.2,69.7 ; JP3.2@25.875,80.23 26.425,80.23 TP5.1@28.945,80.23 ; D4.2@28.975,78.525 TP5.1@28.975,80.2
  POW w0.483: v2(6.2,72.675) 6.2,75.475 7.175,76.45 24.35,76.45 26.425,78.525 JP3.2@26.425,80.23
  Bottom Layer w0.483: 6.2,73.125 v2(6.2,72.675) R79.1@6.2,73.65
VCC_3V9: C72.2 C74.1 D4.1 L9.2 R49.2 | length 8.8
  Top Layer w0.483: R49.2@22.075,77.55 22.075,76.6 L9.2@24.025,74.65 ; L9.2@23.85,74.65 L9.2@24.025,74.65 ; L9.2@24.325,74.55 L9.2@24.225,74.65 ; D4.1@28.8,74.65 L9.2@24.225,74.65 ; L9.2@24.025,74.65 L9.2@24.225,74.65
VCC_430: P4.1 R89.2 U11.1 U11.2 | length 41.9
  Top Layer w0.254: v1(6.1,40.425) R89.2@6.1,40.975 ; v1(18.575,40) v1(22.075,40)
  Bottom Layer w0.254: P4.1@2.54,25.43 4.13,25.43 4.6,25.9 4.6,27.2 6.1,28.7 6.1,34 ; 6.1,35.55 6.1,34 ; 6.1,39.6 6.5,40 v1@6.1,40.4 ; v1(6.1,40.425) 6.1,40.352 6.1,34 ; 6.125,40 v1(18.575,40) ; 22.075,40.25 U11.2@22.075,41.7 v1(22.075,40) 22.425,40 22.725,40.3 U11.1@22.725,41.7
VCC_USB: C73.1 C75.2 D1.2 U6.1 U6.3 | length 10.7
  Top Layer w0.483: D1.2@18.75,78.25 D1.2@19.025,77.975 ; D1.2@19.1,78.05 19.1,78.475 19.075,78.5 19.075,79.975 v2(19.1,80) 19.975,80.875 23.225,80.875 23.453,81.102 U6.1@23.453,82.15 ; 21.548,81.128 U6.3@21.548,82.15
  Bottom Layer w0.483: C73.1@18.9,78.65 19.1,78.85 v2(19.1,80)
VDD_IO1: C25.2 C62.1 C63.2 C64.2 C65.2 C66.2 C67.2 C68.2 C200.2 JP5.1 P1.9 P1.10 R33.2 R34.2 R36.2 R37.2 R38.2 R39.2 R58.2 R62.1 R63.1 R64.2 R65.1 R66.1 R73.1 R96.2 U5.C3 U5.C6 U5.L4 U5.M3 U5.M4 U5.N8 U5.N11 U5.N14 U10.8 | length 115.4
  Top Layer w0.114: U5.C3@18.75,58.375 19.146,58.771 19.927,58.771 v1(19.948,58.75) v1@19.976,58.778 ; v1(24.904,61.971) 26.346,61.971 U5.N8@26.75,62.375 ; v1(26.425,64.45) U5.N11@26.75,64.775
  Top Layer w0.25: U5.C6@18.75,60.775 v1@20.325,60.775 ; v1@21.45,60.175 v1(23.725,60.175) ; v1(24.85,59.475) U5.L4@25.15,59.175 25.155,59.18 25.945,59.18 25.98,59.145 25.98,58.405 U5.M3@25.95,58.375 ; U5.N14@26.75,67.175 v1(26.75,67.725) ; v1(31.1,50.75) v1(33.45,50.75) 35.975,50.75 v1(37.15,50.75) v1(38.325,50.75) ; P1.10@32.75,65.475 P1.10@32.75,65.975 ; P1.9@32.75,66.975 P1.9@32.75,67.475
  Top Layer w0.381: R58.2@9.65,56.525 9.65,55.525 10.212,54.963 C62.1@10.475,54.7 ; C62.1@10.575,54.7 C64.2@12.15,54.7 v1(12.825,54.7)
  POW w0.114: v1(24.904,61.971) v1@24.946,61.971
  POW w0.25: P1.10@32.75,65.475 P1.9@32.75,67.475 ; P1.10@32.825,65.475 35.3,65.475 36.25,64.525 36.25,61.6 37.15,60.7 v1(37.15,50.75)
  POW w0.381: JP5.1@18.42,53.375 22.5,53.375 ; v2(22.525,56.175) 22.525,53.35 22.525,51 23.6,49.925 30.275,49.925 v1(31.1,50.75)
  Bottom Layer w0.25: 17.735,54.06 JP5.1@18.42,53.375 ; v1(19.948,58.75) C65.2@20.75,58.75 ; v1(20.375,60.775) 21.125,60.775 21.425,60.475 21.425,59.25 20.925,58.75 C65.2@20.75,58.75 ; C65.2@20.8,58.7 C65.2@20.75,58.75 ; R38.2@21.925,56.175 v2@22.425,56.175 ; v2(22.525,56.175) 23.651,56.175 ; 23.776,62.125 C25.2@24.425,62.125 ; C25.2@24.425,61.971 v1(24.904,61.971) ; v1(24.85,59.475) 24.75,59.475 24.425,59.8 23.751,59.8 ; R36.2@25.525,56.175 23.651,56.175 ; C68.2@25.793,67.632 25.25,67.088 25.25,64.45 ; C68.2@25.887,67.725 v1(26.75,67.725) ; v1(26.425,64.45) 25.7,64.45 25.25,64.45 ; R34.2@30.375,73.425 R33.2@30.375,71.45 30.375,70.1 32.75,67.725 P1.9@32.75,67.475 ; R66.1@31.1,50.075 v1(31.1,50.75) ; R65.1@32.275,50.075 v1(32.275,50.775) ; U10.8@32.475,45.58 32.475,47.25 32.575,47.35 33.625,47.35 34.125,47.85 34.125,49.45 C200.2@34.75,50.075 v1(34.75,50.725) ; R96.2@32.8,59.825 32.8,60.875 33.325,61.4 v1(36.425,61.4) ; R64.2@33.45,50.075 v1(33.45,50.75) ; R62.1@35.975,50.125 v1(35.975,50.775) ; R63.1@37.15,50.125 v1(37.15,50.75) ; R73.1@38.325,50.125 v1(38.325,50.75) ; 23.651,56.175 23.68,56.204 23.68,57.545 23.375,57.85 23.375,58.905 23.751,59.281 23.751,59.8 ; 23.751,59.8 23.751,63.801 24.4,64.45 25.25,64.45
  Bottom Layer w0.381: v1(12.825,54.7) 17.095,54.7 17.735,54.06
  other v1: 21.45,60.15
WAKEUP: R35.2 U5.A5 | length 3.5
  Top Layer w0.114: R35.2@13.9,59.45 14.075,59.625 16.4,59.625 16.75,59.975 U5.A5@17.15,59.975
pads on no net: D6. D7. D8. D9. D10. D11. D12. D13. D14. J2.0 U2.11 U2.13 U2.14 U2.20 U2.21 U2.22 U2.23 U2.32 U5.A8 U5.A9 U5.A10 U5.B8 U5.C9 U5.D14 U5.E1 U5.E2 U5.F1 U5.G1 U5.G2 U5.H1 U7.0 U10.0 U11.7 U13. U13.6 USB1. USB1.4

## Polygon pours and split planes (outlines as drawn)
P2.4 on Top Layer "Top Layer-No Net" (solid, remove dead copper, pour order 1000): 15.98,17.53 15.75,19.41 15.8,20.96 16.71,24.37 17.66,26.19 19.62,28.55 21.84,30.13 24.35,31.27 26.29,31.48 28.88,31.02 31.52,30.12 33.83,28.7 36.05,26.67 37.66,24.29 38.51,22.51 39.23,19.75 39.41,17.49 38.98,18.93 38.3,20.7 37.05,22.66 35,24.69 32.21,26.33 30.5,26.87 28.58,27.15 25.52,27.03 26.4,26.56 27.91,25.48 28.48,24.63 29.07,23.01 28.9,21.17 28.38,21.43 27.1,22.24 25.78,22.42 23.45,22.14 22.39,21.4 21.82,20.98 21.27,21.08 20.23,21.1 18.48,20.63 17.41,19.78 16.23,18.25 16.08,17.59 15.99,17.53
P2.1 on Top Layer "Top Layer-No Net" (solid, remove dead copper, pour order 1001): 25.36,7.92 23.48,7.69 21.93,7.74 18.52,8.65 16.7,9.6 14.34,11.56 12.76,13.78 11.62,16.29 11.41,18.23 11.87,20.82 12.77,23.46 14.19,25.77 16.22,27.99 18.6,29.6 20.38,30.45 23.14,31.17 25.4,31.35 23.96,30.92 22.19,30.24 20.23,28.99 18.2,26.94 16.56,24.15 16.02,22.44 15.74,20.52 15.86,17.46 16.33,18.34 17.41,19.85 18.26,20.42 19.88,21.01 21.72,20.84 21.46,20.32 20.65,19.04 20.47,17.72 20.75,15.39 21.49,14.33 21.91,13.76 21.81,13.21 21.79,12.17 22.26,10.42 23.11,9.35 24.64,8.17 25.3,8.02 25.36,7.93
P2.2 on Top Layer "Top Layer-No Net" (solid, remove dead copper, pour order 1002): 35.02,17.41 35.25,15.53 35.2,13.98 34.29,10.57 33.34,8.75 31.38,6.39 29.16,4.81 26.65,3.67 24.71,3.46 22.12,3.92 19.48,4.82 17.17,6.24 14.95,8.27 13.34,10.65 12.49,12.43 11.77,15.19 11.59,17.45 12.02,16.01 12.7,14.24 13.95,12.28 16,10.25 18.79,8.61 20.5,8.07 22.42,7.79 25.48,7.91 24.6,8.38 23.09,9.46 22.52,10.31 21.93,11.93 22.1,13.77 22.62,13.51 23.9,12.7 25.22,12.52 27.55,12.8 28.61,13.54 29.18,13.96 29.73,13.86 30.77,13.84 32.52,14.31 33.59,15.16 34.77,16.69 34.92,17.35 35.01,17.41
P2.3 on Top Layer "Top Layer-No Net" (solid, remove dead copper, pour order 1003): 25.5,27 27.38,27.23 28.93,27.18 32.34,26.27 34.16,25.32 36.52,23.36 38.1,21.14 39.24,18.63 39.45,16.69 38.99,14.1 38.09,11.46 36.67,9.15 34.64,6.93 32.26,5.32 30.48,4.47 27.72,3.75 25.46,3.57 26.9,4 28.67,4.68 30.63,5.93 32.66,7.98 34.3,10.77 34.84,12.48 35.12,14.4 35,17.46 34.53,16.58 33.45,15.07 32.6,14.5 30.98,13.91 29.14,14.08 29.4,14.6 30.21,15.88 30.39,17.2 30.11,19.53 29.37,20.59 28.95,21.16 29.05,21.71 29.07,22.75 28.6,24.5 27.75,25.57 26.22,26.75 25.56,26.9 25.5,26.99
P2.5 on Top Layer "Top Layer-No Net" (solid, remove dead copper, pour order 1004): 20.42,16.98 20.62,19.12 21.27,20.31 22.49,21.73 24.17,22.27 26.15,22.44 27.7,21.98 29.37,20.58 30.32,18.41 30.37,16.87 30.19,15.77 29.14,13.9 27.72,13.03 26.46,12.53 23.91,12.57 22.11,13.59 21.09,14.81 20.42,16.99
GND-AIC on Top Layer "POW-No Net" (solid, remove dead copper, pour order 1000): 39.45,84.55 39.45,81.175 38.5,80.225 37.925,79.65 36.65,79.65 36.075,79.075 36.075,77.525 36.075,72.95 36.55,72.475 38.9,70.125 38.9,64.9 38.9,62 39.575,61.325 39.65,61.25 43.4,61.25 43.8,61.25 44.35,60.7 44.45,60.6 44.45,57.975 44.45,56.225 44.55,56.125 44.75,55.925 45.275,55.925 50.75,55.925 50.775,55.95 50.775,84.6 39.45,84.6 39.45,84.525
P2.0 on Top Layer "Top Layer-No Net" (solid, remove dead copper, pour order 1005): -0.09,34.27 50.85,34.25 50.85,0.56 50.81,0.52 0,0.52 0,34.22 -0.05,34.27
GND on Top Layer "POW-No Net" (hatched 90Degree grid 0.127 track 0.127, remove dead copper, pour order 1000): 0,84.5 0,37.4 50.8,37.4 50.8,54 46.1,54 44.7,55.4 44.2,55.9 44.2,58.1 44.2,60.3 43.6,60.9 43.3,61.2 41.8,61.2 39.3,61.2 38.7,61.8 38.6,61.9 38.6,62.4 38.6,70.3 37.4,71.5 35.9,73 35.9,74.8 35.9,79 35.4,79.5 34.8,80.1 34.8,80.9 34.8,84.5 0,84.5
GND-AIC on GND "POW-No Net" (solid, remove dead copper, pour order 1002): 39.45,84.55 39.45,81.175 38.5,80.225 37.925,79.65 36.65,79.65 36.075,79.075 36.075,77.525 36.075,72.95 36.55,72.475 38.9,70.125 38.9,64.9 38.9,62 39.575,61.325 39.65,61.25 43.4,61.25 43.8,61.25 44.35,60.7 44.45,60.6 44.45,57.975 44.45,56.225 44.55,56.125 44.75,55.925 45.275,55.925 50.75,55.925 50.775,55.95 50.775,84.6 39.45,84.6 39.45,84.525
GND on GND "POW-No Net" (hatched 90Degree grid 0.127 track 0.127, remove dead copper, pour order 1001): 0,84.5 0,37.4 50.8,37.4 50.8,54 46.1,54 44.7,55.4 44.2,55.9 44.2,58.1 44.2,60.3 43.6,60.9 43.3,61.2 41.8,61.2 39.3,61.2 38.7,61.8 38.6,61.9 38.6,62.4 38.6,70.3 37.4,71.5 35.9,73 35.9,74.8 35.9,79 35.4,79.5 34.8,80.1 34.8,80.9 34.8,84.5 0,84.5
GND-AIC on POW "POW-No Net" (solid, remove dead copper, pour order 1004): 39.45,84.55 39.45,81.175 38.5,80.225 37.925,79.65 36.65,79.65 36.075,79.075 36.075,77.525 36.075,72.95 36.55,72.475 38.9,70.125 38.9,64.9 38.9,62 39.575,61.325 39.65,61.25 43.4,61.25 43.8,61.25 44.35,60.7 44.45,60.6 44.45,57.975 44.45,56.225 44.55,56.125 44.75,55.925 45.275,55.925 50.75,55.925 50.775,55.95 50.775,84.6 39.45,84.6 39.45,84.525
GND on POW "POW-No Net" (hatched 90Degree grid 0.127 track 0.127, remove dead copper, pour order 1002): 0,84.5 0,37.4 50.8,37.4 50.8,54 46.1,54 44.7,55.4 44.2,55.9 44.2,58.1 44.2,60.3 43.6,60.9 43.3,61.2 41.8,61.2 39.3,61.2 38.7,61.8 38.6,61.9 38.6,62.4 38.6,70.3 37.4,71.5 35.9,73 35.9,74.8 35.9,79 35.4,79.5 34.8,80.1 34.8,80.9 34.8,84.5 0,84.5
GND on Bottom Layer "Top Layer-No Net" (hatched 90Degree grid 1 track 0.24, remove dead copper, pour order 1006): 10.6,31.63 10.6,2.13 10.7,2.03 39.74,2.03 41.15,3.44 41.15,27.72 37.09,31.78 10.65,31.78 10.35,31.48
GND-AIC on Bottom Layer "POW-No Net" (solid, remove dead copper, pour order 1006): 39.45,84.55 39.45,81.175 38.5,80.225 37.925,79.65 36.65,79.65 36.075,79.075 36.075,77.525 36.075,72.95 36.55,72.475 38.9,70.125 38.9,64.9 38.9,62 39.575,61.325 39.65,61.25 43.4,61.25 43.8,61.25 44.35,60.7 44.45,60.6 44.45,57.975 44.45,56.225 44.55,56.125 44.75,55.925 45.275,55.925 50.75,55.925 50.775,55.95 50.775,84.6 39.45,84.6 39.45,84.525
GND on Bottom Layer "POW-No Net" (hatched 90Degree grid 0.127 track 0.127, remove dead copper, pour order 1003): 0,84.5 0,37.4 50.8,37.4 50.8,54 46.1,54 44.7,55.4 44.2,55.9 44.2,58.1 44.2,60.3 43.6,60.9 43.3,61.2 41.8,61.2 39.3,61.2 38.7,61.8 38.6,61.9 38.6,62.4 38.6,70.3 37.4,71.5 35.9,73 35.9,74.8 35.9,79 35.4,79.5 34.8,80.1 34.8,80.9 34.8,84.5 0,84.5

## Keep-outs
Keep-Out Layer:
  lines w0.254: 0,0 50.8,0 50.8,84.5 46.725,84.5 46.725,81.175 42,81.175 42,84.5 0,84.5 0,0

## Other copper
Top Layer:
  rectangle net P2.5: 27.46,16.92 28.64,18.73
  pour cut-out: 2.675,56.25 2.85,56.075 3.65,56.075 3.35,55.775 3.35,53.175 3.325,53.2 2.55,53.2 2.525,53.225 2.525,56.325
  pour cut-out: 6.375,55.725 7.15,55.725 7.475,55.4 7.475,53.226 7.324,53.075 6.25,53.075 6.175,53.15 6.175,55.575 6.4,55.8 6.975,55.8
  pour cut-out: 8.425,56.2 8.475,56.15 8.475,53.3 8.325,53.15 7.425,53.15 7.425,56.125 7.5,56.2
Bottom Layer:
  pour cut-out: 38.025,42.675 39.7,42.675 39.7,46 38.025,46
  pour cut-out: 31.4,45.85 33.35,45.85 33.35,41.85 31.4,41.85
  pour cut-out: 26.45,42.775 27.5,42.775 27.5,40.025 26.45,40.025
  pour cut-out: 29.75,48.4 29.85,48.5 29.85,45.875 26.275,45.875 26.2,45.95 26.2,48.4
  pour cut-out: 45.6,53.725 46.6,53.725 46.6,52.325 46.579,52.346 45.654,52.346 45.6,52.4

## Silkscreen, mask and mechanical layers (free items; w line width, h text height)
Top Overlay:
  lines w0.15: 13,53.025 12.7,53.025 14,51.725 15.2,51.725
  lines w0.152: 13.975,56.575 13.975,58.675 14.1,58.55 ; 14.125,71.35 14.3,71.525 14.825,71.525 ; 20.075,68.25 19.875,68.45 23.25,68.45 ; 20.75,73.7 21.025,73.975 21.025,71.975
  text "3V6" at 30,80.075 h0.6
  text "VBUS" at 9.6,73.425 h0.6
  text "GPIO15" at 33.675,61.675 h0.6
  text "GPIO17" at 29.775,61.325 h0.6 r90
  text "GPIO14" at 33.55,60 h0.6
  text "GND" at 2,59.332 h0.6
  text "1V8" at 4.3,58.625 h0.6
  text "GPIO16" at 29.762,57.975 h0.6 r90
  text "RTCCLKOUT" at 11.5,55.825 h0.6
  text "CLKOUT" at 14.2,54.925 h0.6
  text "1V3" at 28.925,52.6 h0.6
  text "GND" at 45.85,51.125 h0.6
  text "CLK_SEL" at 15.7,51.025 h0.6
Bottom Overlay:
  lines w0.15: 6.5,20.9 7.1,20.9 ; 6.6,12.7 7.2,12.7 ; 10.6,4.7 11.2,4.7 ; 15,29.2 15.6,29.2 ; 27.5,17.7 28.1,17.7 ; 35.4,5 36,5 ; 35.5,29.1 36.1,29.1 ; 39.5,21.2 40.1,21.2 ; 43.6,13.2 44.2,13.2 ; 6.5,21.2 6.8,20.9 7.1,21.2 6.5,21.2 ; 6.6,13 6.9,12.7 7.2,13 6.6,13 ; 10.6,5 10.9,4.7 11.2,5 10.6,5 ; 15,29.5 15.3,29.2 15.6,29.5 15,29.5 ; 27.5,17.4 28.1,17.4 27.8,17.7 27.5,17.4 ; 35.4,4.7 35.7,5 36,4.7 35.4,4.7 ; 35.5,28.8 35.8,29.1 36.1,28.8 35.5,28.8 ; 39.5,20.9 39.8,21.2 40.1,20.9 39.5,20.9 ; 43.6,12.9 43.9,13.2 44.2,12.9 43.6,12.9
  lines w0.152: 12.225,68.4 13,67.625 13,70.75 ; 16.625,72.625 16.625,61.6 16.8,61.775 ; 20.05,66.875 19.85,67.075 20.8,67.075 ; 23,59.375 23.3,59.075 30.5,59.075 ; 23.85,57.65 23.275,57.075 27.075,57.075 ; 26.75,61.25 26.475,61.525 32.3,61.525 ; 27.675,74.175 27.4,74.45 29.7,74.45
  lines w0.254: 45,33.5 45,37.8 45.8,37
  text "430BOOST-C55AUDIO1_V2.0" at 35.4,26.4 h1
  text "Audio Capacitive Touch Booster Pack" at 38.2,24.6 h1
